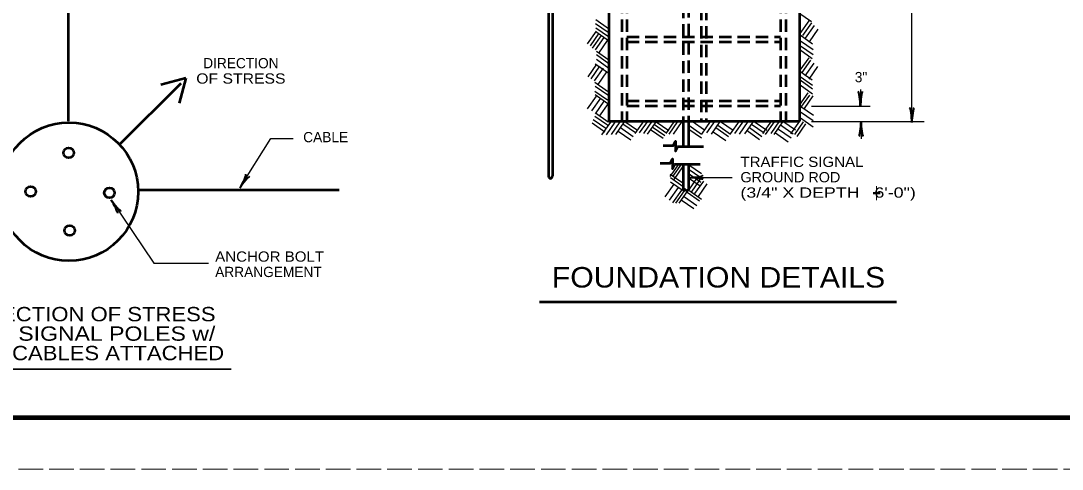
# Model space of a CAD drawing. Extents: x -560 to 120, y 26 to 466.
# Drawn here: x -268.1 to -64.9, y 25.8 to 113.4 of the extents above; entities that cross this region are included whole.
import ezdxf
from ezdxf.enums import TextEntityAlignment as Align

# ---------------------------------------------------------------- set-up
doc = ezdxf.new("R2010")
doc.units = 0
doc.header["$LTSCALE"] = 0.8
doc.linetypes.add('LONG_DASHED', pattern=[7.5, 6, -1.5])
doc.linetypes.add('MEDIUM_DASHED', pattern=[4.5, 3, -1.5])
doc.layers.add('1', color=7, linetype='Continuous', lineweight=53)
doc.layers.add('61', color=7, linetype='Continuous', lineweight=35)

msp = doc.modelspace()

# ---------------------------------------------------------------- linework, layer by layer
at = {"layer": '1', "linetype": 'MEDIUM_DASHED'}
for p, q in [((-138.8254, 166.7043), (-138.8254, 93.7352)), ((-137.8254, 166.7793), (-137.8254, 93.7352)), ((-150.8254, 164.0374), (-150.8254, 93.7352)), ((-149.8254, 164.0374), (-149.8254, 93.7352)), ((-119.8254, 164.0374), (-119.8254, 93.7352)), ((-118.8254, 164.0374), (-118.8254, 93.7352)), ((-135.3254, 148.2887), (-135.3254, 93.7352)), ((-134.3254, 148.2887), (-134.3254, 93.7352)), ((-149.8254, 110.2352), (-119.8254, 110.2352)), ((-149.8254, 109.2352), (-119.8254, 109.2352)), ((-149.8254, 97.7352), (-119.8254, 97.7352)), ((-149.8254, 96.7352), (-119.8254, 96.7352))]:
    msp.add_line(p, q, dxfattribs=at)
at = {"layer": '1', "lineweight": 25}
for p, q in [((-94.2062, 93.4865), (-94.2062, 166.6995)), ((-116.2467, 114.9399), (-113.7892, 113.2193)), ((-155.9327, 112.8393), (-153.4752, 111.1187)), ((-155.8577, 113.5896), (-153.4002, 111.8689)), ((-155.8577, 112.0141), (-153.4002, 110.2934)), ((-115.9941, 110.8899), (-114.2734, 113.3473)), ((-115.4689, 110.5148), (-113.7482, 112.9723)), ((-114.9437, 109.9897), (-113.2231, 112.4471)), ((-157.4805, 108.8642), (-155.7598, 111.3217)), ((-156.9554, 108.4892), (-155.2347, 110.9466)), ((-156.5052, 108.039), (-154.7846, 110.4964)), ((-155.9801, 107.6639), (-154.2594, 110.1213)), ((-155.8577, 111.2639), (-153.4002, 109.5433)), ((-116.0217, 110.5887), (-113.5642, 108.8681)), ((-114.1936, 109.2395), (-112.4729, 111.6969)), ((-155.3049, 107.0637), (-153.5842, 109.5212)), ((-116.0967, 107.738), (-113.6392, 106.0173)), ((-115.9467, 109.4634), (-113.4892, 107.7428)), ((-115.9467, 108.4882), (-113.4892, 106.7675)), ((-155.7827, 107.4379), (-153.3252, 105.7172)), ((-155.7827, 106.7627), (-153.3252, 105.0421)), ((-155.7827, 105.8625), (-153.3252, 104.1418)), ((-115.9941, 103.6879), (-114.2734, 106.1453)), ((-115.619, 103.2378), (-113.8983, 105.6953)), ((-157.4055, 102.4126), (-155.6848, 104.87)), ((-156.8053, 102.0375), (-155.0847, 104.4949)), ((-156.1302, 101.6624), (-154.4095, 104.1198)), ((-156.0077, 104.9622), (-153.5502, 103.2416)), ((-115.0188, 102.6377), (-113.2982, 105.0951)), ((-114.2686, 101.9625), (-112.5479, 104.4199)), ((-155.455, 100.9122), (-153.7343, 103.3696)), ((-116.0967, 103.5368), (-113.6392, 101.8162)), ((-116.0217, 102.4865), (-113.5642, 100.7658)), ((-116.0217, 101.8113), (-113.5642, 100.0907)), ((-156.0827, 101.3612), (-153.6252, 99.6406)), ((-156.0827, 99.6358), (-153.6252, 97.9151)), ((-156.0077, 100.611), (-153.5502, 98.8903)), ((-116.0217, 100.8361), (-113.5642, 99.1154)), ((-104.2589, 99.9382), (-104.2589, 96.6591)), ((-157.4805, 96.1858), (-155.7598, 98.6432)), ((-156.6552, 95.8107), (-154.9346, 98.2681)), ((-156.0077, 98.9606), (-153.5502, 97.2399)), ((-155.9801, 95.2105), (-154.2594, 97.6679)), ((-116.1441, 96.8611), (-114.4234, 99.3185)), ((-115.844, 96.411), (-114.1233, 98.8684)), ((-115.1688, 96.2609), (-113.4482, 98.7183)), ((-155.1548, 94.7604), (-153.4342, 97.2178)), ((-115.9467, 95.5847), (-113.4892, 93.864)), ((-115.8717, 96.6349), (-113.4142, 94.9142)), ((-113.812, 96.6591), (-102.312, 96.6591)), ((-156.3828, 94.0842), (-153.9253, 92.3635)), ((-156.0828, 94.7593), (-153.6252, 93.0387)), ((-155.9327, 95.3595), (-153.4752, 93.6388)), ((-154.7048, 91.0844), (-152.9842, 93.5418)), ((-153.8046, 91.0844), (-152.0839, 93.5418)), ((-152.8293, 91.1594), (-151.1086, 93.6168)), ((-152.0041, 91.1594), (-150.2834, 93.6168)), ((-150.2311, 93.7091), (-147.7736, 91.9884)), ((-148.1779, 91.3845), (-146.4572, 93.8419)), ((-147.3527, 91.4595), (-145.632, 93.9169)), ((-146.5274, 91.3846), (-144.8067, 93.842)), ((-145.7773, 91.2345), (-144.0566, 93.6919)), ((-144.0794, 93.634), (-141.6219, 91.9133)), ((-142.1763, 91.3845), (-140.4557, 93.8419)), ((-141.5762, 91.2345), (-139.8555, 93.6919)), ((-140.7509, 91.2345), (-139.0302, 93.6919)), ((-137.1025, 93.7841), (-134.645, 92.0634)), ((-135.1994, 91.2345), (-133.4787, 93.6919)), ((-134.2242, 91.4596), (-132.5035, 93.917)), ((-133.3239, 91.2345), (-131.6033, 93.6919)), ((-131.5509, 93.7091), (-129.0934, 91.9884)), ((-129.5728, 91.3095), (-127.8522, 93.7669)), ((-128.7476, 91.3845), (-127.0269, 93.8419)), ((-127.8473, 91.2345), (-126.1267, 93.6919)), ((-126.7971, 91.3095), (-125.0764, 93.7669)), ((-124.9492, 93.7091), (-122.4917, 91.9884)), ((-123.271, 91.3845), (-121.5503, 93.8419)), ((-122.7458, 91.1594), (-121.0252, 93.6168)), ((-121.6956, 91.3845), (-119.9749, 93.8419)), ((-121.0954, 91.1594), (-119.3747, 93.6168)), ((-119.3976, 93.7842), (-116.9401, 92.0635)), ((-117.7946, 91.3095), (-116.0739, 93.7669)), ((-117.0443, 91.1595), (-115.3237, 93.6169)), ((-115.9467, 94.3843), (-113.4892, 92.6637)), ((-113.812, 93.6773), (-91.812, 93.6773)), ((-104.1088, 93.6773), (-104.1088, 90.3365)), ((-156.6078, 93.409), (-154.1503, 91.6883)), ((-151.5064, 91.8336), (-149.0489, 90.1129)), ((-151.0563, 92.5087), (-148.5988, 90.7881)), ((-150.6062, 93.2589), (-148.1487, 91.5382)), ((-145.2047, 92.1337), (-142.7472, 90.413)), ((-144.9046, 92.6587), (-142.4471, 90.9381)), ((-144.4545, 93.1089), (-141.997, 91.3882)), ((-137.7027, 92.9588), (-135.2452, 91.2382)), ((-137.7027, 92.2087), (-135.2452, 90.488)), ((-132.9763, 91.6835), (-130.5188, 89.9628)), ((-132.4512, 92.5087), (-129.9937, 90.7881)), ((-132.0761, 92.9588), (-129.6186, 91.2382)), ((-126.3746, 91.9086), (-123.9171, 90.1879)), ((-125.9244, 92.5087), (-123.4669, 90.7881)), ((-125.4743, 93.1839), (-123.0168, 91.4633)), ((-120.2228, 92.2087), (-117.7653, 90.4881)), ((-119.8477, 93.0339), (-117.3902, 91.3132)), ((-116.5943, 90.7844), (-114.8736, 93.2418)), ((-225.3448, 80.7157), (-219.3484, 90.3874)), ((-219.3484, 90.3874), (-214.968, 90.3874)), ((-120.823, 91.4585), (-118.3655, 89.7378)), ((-141.3511, 82.9822), (-139.6304, 85.4396)), ((-140.826, 82.9822), (-139.1053, 85.4396)), ((-141.3787, 83.4312), (-138.9212, 81.7106)), ((-140.6009, 82.382), (-138.8802, 84.8394)), ((-137.8527, 84.4815), (-135.3953, 82.7608)), ((-137.8527, 83.5812), (-135.3953, 81.8606)), ((-137.7027, 85.2317), (-135.2452, 83.5111)), ((-142.3263, 79.0061), (-140.6057, 81.4635)), ((-141.3037, 82.7561), (-138.8462, 81.0354)), ((-141.3037, 81.9308), (-138.8462, 80.2102)), ((-137.8307, 82.7538), (-129.2783, 82.7538)), ((-137.8243, 82.7061), (-135.5452, 81.1104)), ((-137.7501, 80.2815), (-136.0294, 82.7389)), ((-137.2249, 79.9063), (-135.5042, 82.3637)), ((-136.5497, 79.6063), (-134.8291, 82.0637)), ((-135.8746, 79.0812), (-134.1539, 81.5386)), ((-141.5011, 78.3308), (-139.7804, 80.7882)), ((-140.826, 77.8058), (-139.1053, 80.2632)), ((-140.3008, 77.7308), (-138.5802, 80.1882)), ((-139.6257, 77.7308), (-137.905, 80.1882)), ((-138.0778, 79.9052), (-135.6202, 78.1846)), ((-137.7027, 80.2804), (-135.2452, 78.5597)), ((-139.2031, 78.4048), (-136.7456, 76.6842)), ((-138.6029, 79.005), (-136.1454, 77.2843))]:
    msp.add_line(p, q, dxfattribs=at)
at = {"layer": '1'}
for p, q in [((-116.1271, 164.5293), (-116.1271, 93.7351)), ((-165.1448, 140.7231), (-165.1448, 83.0187)), ((-164.3448, 140.7231), (-164.3448, 83.0187)), ((-258.9058, 134.7319), (-258.9058, 93.7319)), ((-235.9372, 102.1299), (-240.7668, 100.8357)), ((-235.9372, 102.1299), (-237.2313, 97.3002)), ((-248.8257, 89.1829), (-236.8249, 101.1838)), ((-138.8243, 93.7507), (-138.8243, 88.7507)), ((-137.8257, 93.76), (-137.8257, 88.76)), ((-138.8243, 85.35), (-138.8243, 80.35)), ((-137.8243, 85.35), (-137.8243, 80.35)), ((-164.7449, 82.5918), (-164.7449, 82.5027)), ((-244.9785, 80.377), (-205.9785, 80.377)), ((-138.3174, 80.3148), (-138.3492, 80.344)), ((-166.8687, 58.4753), (-97.2327, 58.4753))]:
    msp.add_line(p, q, dxfattribs=at)
at = {"layer": '1', "lineweight": 35}
msp.add_line((-282.7947, 45.3173), (-227.0857, 45.3173), dxfattribs=at)
at = {"layer": '1'}
for points in [[(-153.3254, 163.6995), (-153.3254, 93.7352), (-116.1271, 93.7352)], [(-142.7341, 88.9814), (-140.7341, 88.9814), (-140.3115, 89.8877), (-140.3115, 87.8877), (-139.8889, 88.7941), (-134.8889, 88.7941)], [(-143.3341, 85.5312), (-141.3341, 85.5312), (-140.9115, 86.4375), (-140.9115, 84.4375), (-140.4889, 85.3438), (-135.4889, 85.3438)]]:
    msp.add_lwpolyline(points, dxfattribs=at)
at = {"layer": '1', "lineweight": 25}
msp.add_lwpolyline([(-250.4912, 78.3945), (-242.1736, 66.0147), (-231.4717, 66.0147)], dxfattribs=at)
at = {"layer": '1'}
for centre, radius in [((-258.7122, 79.9902), 13.5), ((-258.7813, 87.5858), 1), ((-266.1981, 80.0342), 1), ((-250.8253, 79.7645), 1), ((-258.5791, 72.4153), 1)]:
    msp.add_circle(centre, radius, dxfattribs=at)
for centre, start, end in [((-164.6001, 83.1257), 191.11811, 254.886), ((-164.8891, 83.1256), 285.114, 348.88189)]:
    msp.add_arc(centre, 0.5552, start, end, dxfattribs=at)
at = {"layer": '1', "lineweight": 40}
for centre, major_axis, ratio, start_param, end_param in [((-104.5352, 97.7503), (0.1562, -1.7857), 0.122415, 0.89635335, 3.14159265), ((-104.0473, 97.7796), (0.1757, 1.7565), 0.07063, 6.28230741, 8.55970261), ((-94.4825, 94.5777), (0.1562, -1.7857), 0.122415, 0.89635335, 3.14159265), ((-93.9946, 94.607), (0.1757, 1.7565), 0.07063, 6.28230741, 8.55970261), ((-104.3204, 92.5568), (-0.1757, -1.7565), 0.07063, 6.28230741, 8.55970261), ((-103.8325, 92.5861), (-0.1562, 1.7857), 0.122415, 0.89635335, 3.14159265), ((-225.0047, 81.7888), (-0.8082, -1.6), 0.122415, 0.89635335, 3.14159265), ((-224.5746, 81.5566), (1.0748, 1.4003), 0.07063, 6.28230741, 8.55970261), ((-136.7103, 82.5422), (1.7565, -0.1757), 0.07063, 6.28230741, 8.55970261), ((-136.7396, 83.0301), (-1.7857, -0.1562), 0.122415, 0.89635335, 3.14159265), ((-250.042, 77.3464), (0.8338, -1.5559), 0.07063, 6.28230741, 8.55970261), ((-249.6534, 77.6428), (-1.1255, 1.3951), 0.122415, 0.89635335, 3.14159265)]:
    msp.add_ellipse(centre, major_axis=major_axis, ratio=ratio, start_param=start_param, end_param=end_param, dxfattribs=at)
at = {"layer": '1'}
for centre, major_axis, ratio, start_param, end_param in [((-138.5627, 80.6305), (-0.261, -0.2742), 0.942572, 0, 1.41077795), ((-138.558, 80.0798), (-0.261, 0.2742), 0.870662, 4.86038393, 6.28318531), ((-138.0821, 80.6305), (0.2855, 0.2717), 0.960356, 3.31803875, 4.71238898)]:
    msp.add_ellipse(centre, major_axis=major_axis, ratio=ratio, start_param=start_param, end_param=end_param, dxfattribs=at)
at = {"layer": '61', "lineweight": 158}
msp.add_line((109.2791, 35.8027), (-529.7809, 35.8227), dxfattribs=at)
at = {"layer": '61', "linetype": 'LONG_DASHED', "lineweight": 13}
msp.add_line((120.2191, 25.8227), (-559.8409, 25.8027), dxfattribs=at)

# ---------------------------------------------------------------- texts
at = {"layer": '1'}
msp.add_text('DIRECTION', height=2, dxfattribs=at).set_placement((-225.1611, 104.0906), align=Align.CENTER)
for s, height, width, p in [('OF STRESS', 2, 1.15, (-225.1611, 101.0906)), ('DIRECTION OF STRESS', 2.8, 1.15, (-254.7468, 54.681)), ('FOR SIGNAL POLES w/', 2.8, 1.2, (-254.7468, 50.881)), ('TWO CABLES ATTACHED', 2.8, 1.15, (-254.7468, 47.081))]:
    msp.add_text(s, height=height, dxfattribs=dict(at, width=width)).set_placement(p, align=Align.CENTER)
for s, p in [('3"', (-105.3461, 101.3662)), ('ARRANGEMENT', (-230.1807, 63.3213))]:
    msp.add_text(s, height=2, dxfattribs=at).set_placement(p)
msp.add_text('CABLE', height=2, dxfattribs=at).set_placement((-204.2278, 89.6472), align=Align.RIGHT)
for s, height, width, p in [('TRAFFIC SIGNAL', 2, 1.1, (-127.6668, 84.8212)), ('GROUND ROD', 2, 1.05, (-127.6668, 81.8212)), ('(3/4" X DEPTH   6\'-0")', 2, 1.3, (-127.6668, 78.8212)), ('+', 4, 0.55, (-101.9492, 77.7766)), ('ANCHOR BOLT', 2, 1.1, (-230.1807, 66.3213)), ('FOUNDATION DETAILS', 4, 1.1, (-164.4679, 61.2771))]:
    msp.add_text(s, height=height, dxfattribs=dict(at, width=width)).set_placement(p)

doc.saveas('drawing.dxf')
